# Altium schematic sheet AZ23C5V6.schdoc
size 127 x 101 mm
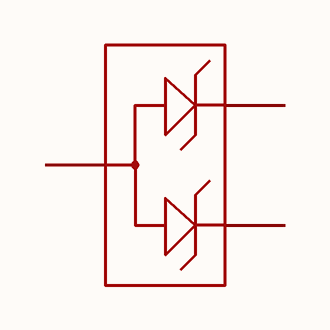
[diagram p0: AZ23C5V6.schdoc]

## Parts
D?  az23c5v6  [SOT-23-3_L2.9-W1.3-P0.95-LS2.4-BR]  (value not drawn)

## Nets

Not connected (* = marked no-connect by the designer): D? 1 2 3

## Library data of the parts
D? = az23c5v6: 二极管配置:1对共阳极;稳压值(标称值):5.6V;稳压值(范围):5.2V~6V;耗散功率(Pd):300mW;; Manufacturer: CJ(江苏长电/长晶); AddInBom: yes; ModelId: c62791f0466c4ae2a892c056b845b0ca; ModelName: SOT-23-3P_L2.9-W1.3-H1.0-LS2.4-P0.95; ModelTransform: 98.425,114.173,0,180,0,0,0.0005,-0.0005,0; Diode Configuration: 1对共阳极; Zener Voltage(Nom): 5.6V; Reverse Leakage Current (Ir): 100nA@1V; Pd - Power Dissipation: 300mW; Impedance(Zzt): 40Ω; Impedance(Zzk): 400Ω; Operating Junction Temperature Range: -65℃~+150℃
